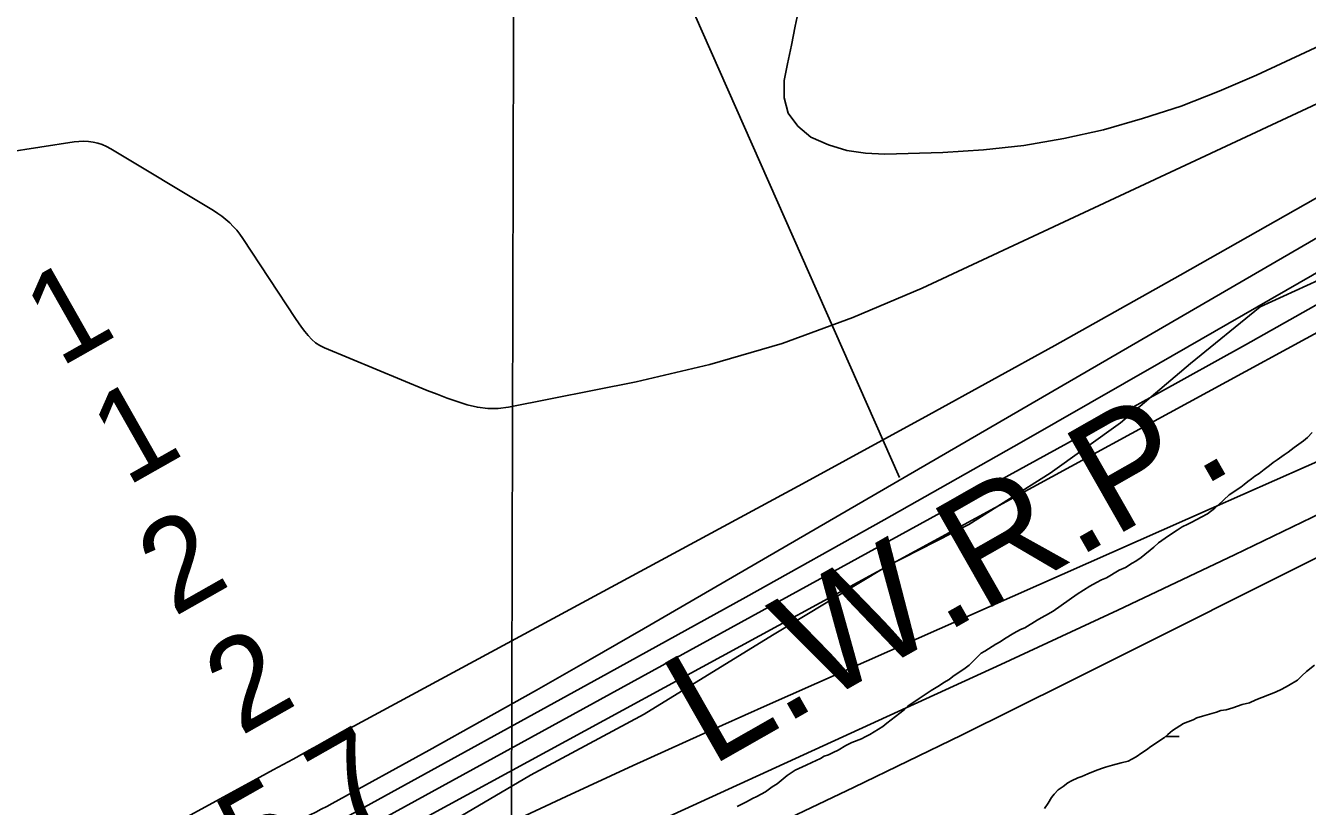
# Model space of a CAD drawing. Extents: x 3177385 to 3215275, y 903885 to 929304.
# Drawn here: x 3191696 to 3192634, y 910384 to 910956 of the extents above; entities that cross this region are included whole.
import ezdxf

# ---------------------------------------------------------------- set-up
doc = ezdxf.new("R2010")
doc.units = 0
for name, color, linetype in [('V-GRID-MAJR', 7, 'Continuous'), ('V-RIVR-EDGE', 7, 'Continuous'), ('V-RIVR-RANG', 7, 'Continuous'), ('V-SITE-VEGE', 7, 'Continuous'), ('V-TOPO-DPTH', 7, 'Continuous'), ('V-TOPO-MAJR', 7, 'Continuous'), ('V-TOPO-MINR', 7, 'Continuous'), ('V-TOPO-WATR', 7, 'Continuous'), ('V-TOPO-WATR-IDEN', 7, 'Continuous'), ('V-WETL-SWMP', 7, 'Continuous')]:
    doc.layers.add(name, color=color, linetype=linetype)

msp = doc.modelspace()

# ---------------------------------------------------------------- linework, layer by layer
at = {"layer": 'V-GRID-MAJR'}
msp.add_spline([(3192048.7, 909312.78), (3192063.69, 915372.62), (3192078.68, 921435.55), (3192093.67, 927498.52), (3192093.68, 927501.56)], degree=3, dxfattribs=at)
at = {"layer": 'V-RIVR-EDGE'}
msp.add_lwpolyline([(3191682.14, 910203.16), (3191755.71, 910245.57), (3191792.71, 910266.35), (3191827.54, 910288.86), (3191886.7, 910308.28), (3191936.3, 910326.85), (3191958.94, 910340.7), (3191997.69, 910367.55), (3192065.17, 910407.38), (3192148.3, 910451.94), (3192242.33, 910509.96), (3192325.92, 910560.17), (3192385.98, 910590.89), (3192445.62, 910628.56), (3192497.01, 910665.38), (3192548.4, 910708.72), (3192599.37, 910750.32), (3192650.72, 910773.67)], dxfattribs=at)
at = {"layer": 'V-RIVR-RANG'}
msp.add_line((3192335.41, 910625.19), (3191971.39, 911448.29), dxfattribs=at)
at = {"layer": 'V-SITE-VEGE'}
for p, q in [((3192637.48, 910658.32), (3192633.91, 910654.68)), ((3192624.36, 910647.24), (3192619.92, 910643.84)), ((3192631.01, 910652.12), (3192624.36, 910647.24)), ((3192633.91, 910654.68), (3192631.01, 910652.12)), ((3192608.84, 910636.22), (3192606.17, 910634.09)), ((3192611.72, 910638.12), (3192608.84, 910636.22)), ((3192617.04, 910641.94), (3192611.72, 910638.12)), ((3192619.92, 910643.84), (3192617.04, 910641.94)), ((3192598.62, 910628.14), (3192595.52, 910626.24)), ((3192602.18, 910631.12), (3192598.62, 910628.14)), ((3192606.17, 910634.09), (3192602.18, 910631.12)), ((3192585.31, 910618.16), (3192576.68, 910612.66)), ((3192587.76, 910620.29), (3192585.31, 910618.16)), ((3192590.42, 910622.42), (3192587.76, 910620.29)), ((3192593.08, 910624.32), (3192590.42, 910622.42)), ((3192595.52, 910626.24), (3192593.08, 910624.32)), ((3192576.68, 910612.66), (3192568.65, 910604.97)), ((3192560.87, 910598.59), (3192556.24, 910596.29)), ((3192566.2, 910602.84), (3192560.87, 910598.59)), ((3192568.65, 910604.97), (3192566.2, 910602.84)), ((3192542.33, 910589.16), (3192538.57, 910586.83)), ((3192546.52, 910591.03), (3192542.33, 910589.16)), ((3192549.39, 910592.5), (3192546.52, 910591.03)), ((3192556.24, 910596.29), (3192549.39, 910592.5)), ((3192532.14, 910582.6), (3192525.05, 910577.52)), ((3192538.57, 910586.83), (3192532.14, 910582.6)), ((3192521.48, 910574.31), (3192512.15, 910566.65)), ((3192525.05, 910577.52), (3192521.48, 910574.31)), ((3192505.73, 910562.64), (3192500.86, 910559.47)), ((3192508.38, 910564.11), (3192505.73, 910562.64)), ((3192512.15, 910566.65), (3192508.38, 910564.11)), ((3192486.94, 910551.9), (3192483.2, 910550.46)), ((3192496.23, 910557.38), (3192486.94, 910551.9)), ((3192500.86, 910559.47), (3192496.23, 910557.38)), ((3192474.58, 910545.83), (3192465.29, 910539.92)), ((3192479.44, 910548.35), (3192474.58, 910545.83)), ((3192483.2, 910550.46), (3192479.44, 910548.35)), ((3192465.29, 910539.92), (3192447.77, 910527.41)), ((3192442.24, 910524.25), (3192438.93, 910522.57)), ((3192447.77, 910527.41), (3192442.24, 910524.25)), ((3192426.98, 910515.18), (3192423.9, 910513.94)), ((3192436.06, 910520.89), (3192426.98, 910515.18)), ((3192438.93, 910522.57), (3192436.06, 910520.89)), ((3192409.08, 910504.86), (3192405.76, 910503.19)), ((3192412.18, 910507.2), (3192409.08, 910504.86)), ((3192419.04, 910511.42), (3192412.18, 910507.2)), ((3192423.9, 910513.94), (3192419.04, 910511.42)), ((3192395.14, 910496.65), (3192390.68, 910492.37)), ((3192397.79, 910498.12), (3192395.14, 910496.65)), ((3192405.76, 910503.19), (3192397.79, 910498.12)), ((3192386.22, 910487.88), (3192383.33, 910485.76)), ((3192388.45, 910490.02), (3192386.22, 910487.88)), ((3192390.68, 910492.37), (3192388.45, 910490.02)), ((3192371.58, 910477.28), (3192367.83, 910475.17)), ((3192374.47, 910479.62), (3192371.58, 910477.28)), ((3192383.33, 910485.76), (3192374.47, 910479.62)), ((3192358.53, 910469.26), (3192352.77, 910465.45)), ((3192364.72, 910473.06), (3192358.53, 910469.26)), ((3192367.83, 910475.17), (3192364.72, 910473.06)), ((3192341.47, 910457.83), (3192338.79, 910455.26)), ((3192349.67, 910463.55), (3192341.47, 910457.83)), ((3192352.77, 910465.45), (3192349.67, 910463.55)), ((3192335.68, 910452.71), (3192326.14, 910445.49)), ((3192338.79, 910455.26), (3192335.68, 910452.71)), ((3192323.03, 910442.94), (3192313.51, 910437.02)), ((3192326.14, 910445.49), (3192323.03, 910442.94)), ((3192300.5, 910431.19), (3192296.09, 910429.09)), ((3192307.55, 910433.87), (3192300.5, 910431.19)), ((3192310.2, 910435.35), (3192307.55, 910433.87)), ((3192313.51, 910437.02), (3192310.2, 910435.35)), ((3192280.2, 910421.14), (3192277.55, 910419.66)), ((3192283.28, 910422.16), (3192280.2, 910421.14)), ((3192286.81, 910423.84), (3192283.28, 910422.16)), ((3192290.34, 910425.72), (3192286.81, 910423.84)), ((3192296.09, 910429.09), (3192290.34, 910425.72)), ((3192259.02, 910410.89), (3192253.04, 910407.08)), ((3192266.96, 910414.65), (3192259.02, 910410.89)), ((3192271.15, 910416.74), (3192266.96, 910414.65)), ((3192277.55, 910419.66), (3192271.15, 910416.74)), ((3192253.04, 910407.08), (3192245.7, 910400.91)), ((3192237.28, 910395.19), (3192230.87, 910391.62)), ((3192242.17, 910398.8), (3192237.28, 910395.19)), ((3192245.7, 910400.91), (3192242.17, 910398.8)), ((3192223.37, 910387.84), (3192216.53, 910384.5)), ((3192227.79, 910390.15), (3192223.37, 910387.84)), ((3192230.87, 910391.62), (3192227.79, 910390.15))]:
    msp.add_line(p, q, dxfattribs=at)
at = {"layer": 'V-TOPO-DPTH'}
for points in [[(3192750.22, 910991.65), (3192596.7, 910919.95), (3192569.34, 910908.1), (3192541.61, 910897.31), (3192513.31, 910888.11), (3192484.63, 910879.96), (3192455.54, 910873.57), (3192426.26, 910868.47), (3192396.71, 910865.29), (3192366.98, 910863.39), (3192324.53, 910862.06), (3192310.47, 910862.73), (3192296.72, 910864.79), (3192283.47, 910868.96), (3192270.53, 910874.54), (3192260.8, 910882.61), (3192253.83, 910891.99), (3192251.01, 910903.33), (3192250.96, 910915.98), (3192253.46, 910928.15), (3192256.28, 910941.95), (3192259.06, 910955.76), (3192261.79, 910969.57)], [(3192750.22, 910991.65), (3192596.7, 910919.95), (3192569.34, 910908.1), (3192541.61, 910897.31), (3192513.31, 910888.11), (3192484.63, 910879.96), (3192455.54, 910873.57), (3192426.26, 910868.47), (3192396.71, 910865.29), (3192366.98, 910863.39), (3192324.53, 910862.06), (3192310.47, 910862.73), (3192296.72, 910864.79), (3192283.47, 910868.96), (3192270.53, 910874.54), (3192260.8, 910882.61), (3192253.83, 910891.99), (3192251.01, 910903.33), (3192250.96, 910915.98), (3192253.46, 910928.15), (3192256.28, 910941.95), (3192259.06, 910955.76), (3192261.79, 910969.57)], [(3190594.76, 909767.6), (3190671.75, 909798.31), (3190886.03, 909887.07), (3190887.1, 909887.53), (3190890.24, 909888.99), (3191053.07, 909970.07), (3191135.29, 910011.58), (3191217.19, 910053.7), (3191298.62, 910096.72), (3191379.74, 910140.34), (3191862.17, 910403.27), (3191876.76, 910411.21), (3191891.35, 910419.14), (3191905.95, 910427.05), (3191920.56, 910434.96), (3192264.2, 910620.72), (3192356.7, 910671.14), (3192448.97, 910721.98), (3192540.88, 910773.46), (3192632.56, 910825.36), (3192780.37, 910909.72)], [(3192780.37, 910909.72), (3192632.56, 910825.36), (3192540.88, 910773.46), (3192448.97, 910721.98), (3192356.7, 910671.14), (3192264.2, 910620.72), (3191920.56, 910434.96), (3191905.95, 910427.05), (3191891.35, 910419.14), (3191876.76, 910411.21), (3191862.17, 910403.27), (3191379.74, 910140.34), (3191298.62, 910096.72), (3191217.19, 910053.7), (3191135.29, 910011.58), (3191053.07, 909970.07), (3190890.24, 909888.99), (3190887.1, 909887.53), (3190886.03, 909887.07), (3190671.75, 909798.31), (3190594.76, 909767.6)], [(3190773.81, 909825.22), (3190881.11, 909873.05), (3190887.07, 909875.73), (3190893.01, 909878.44), (3190898.94, 909881.19), (3190904.85, 909883.96), (3191537.07, 910183.08), (3191601.03, 910213.58), (3191664.85, 910244.35), (3191728.49, 910275.51), (3191791.99, 910306.94), (3191898.29, 910359.95), (3191908.52, 910365.13), (3191918.71, 910370.39), (3191928.83, 910375.77), (3191938.91, 910381.24), (3192121.67, 910481.72), (3192222.94, 910537.78), (3192323.99, 910594.23), (3192424.7, 910651.27), (3192525.2, 910708.7), (3192802.32, 910868.12)], [(3192802.32, 910868.12), (3192525.2, 910708.7), (3192424.7, 910651.27), (3192323.99, 910594.23), (3192222.94, 910537.78), (3192121.67, 910481.72), (3191938.91, 910381.24), (3191928.83, 910375.77), (3191918.71, 910370.39), (3191908.52, 910365.13), (3191898.29, 910359.95), (3191791.99, 910306.94), (3191728.49, 910275.51), (3191664.85, 910244.35), (3191601.03, 910213.58), (3191537.07, 910183.08), (3190904.85, 909883.96), (3190898.94, 909881.19), (3190893.01, 909878.44), (3190887.07, 909875.73), (3190881.11, 909873.05), (3190773.81, 909825.22)], [(3189907.85, 909317.76), (3190786.54, 909802.18), (3190846.26, 909830.37), (3190874.99, 909843.88), (3190903.74, 909857.33), (3190932.53, 909870.71), (3190961.34, 909884.03), (3191160.92, 909975.94), (3191289.34, 910035.62), (3191417.47, 910095.9), (3191545.17, 910157.07), (3191672.6, 910218.83), (3191886.81, 910323.58), (3191909.55, 910334.88), (3191932.19, 910346.38), (3191954.68, 910358.18), (3191977.06, 910370.17), (3192774.87, 910804.33)]]:
    msp.add_lwpolyline(points, dxfattribs=at)
at = {"layer": 'V-TOPO-MAJR'}
msp.add_lwpolyline([(3191330.66, 909999.44), (3191930.38, 910227.54), (3191958.09, 910239.21), (3191985.69, 910251.11), (3192013.15, 910263.35), (3192040.51, 910275.81), (3192144.35, 910323.91), (3192223.38, 910360.95), (3192302.17, 910398.48), (3192380.62, 910436.73), (3192458.83, 910475.47), (3192878.95, 910685.93)], dxfattribs=at)
at = {"layer": 'V-TOPO-MINR'}
for points in [[(3192261.79, 910969.57), (3192259.06, 910955.76), (3192256.28, 910941.95), (3192253.46, 910928.15), (3192250.96, 910915.98), (3192251.01, 910903.33), (3192253.83, 910891.99), (3192260.8, 910882.61), (3192270.53, 910874.54), (3192283.47, 910868.96), (3192296.72, 910864.79), (3192310.47, 910862.73), (3192324.53, 910862.06), (3192366.98, 910863.39), (3192396.71, 910865.29), (3192426.26, 910868.47), (3192455.54, 910873.57), (3192484.63, 910879.96), (3192513.31, 910888.11), (3192541.61, 910897.31), (3192569.34, 910908.1), (3192596.7, 910919.95), (3192750.22, 910991.65)], [(3191680.9, 910863.18), (3191731.16, 910870.99), (3191734.63, 910871.36), (3191738.09, 910871.49), (3191741.56, 910871.29), (3191745.01, 910870.86), (3191748.4, 910870.07), (3191751.7, 910869.04), (3191754.87, 910867.65), (3191757.94, 910866.03), (3191833.13, 910820.75), (3191836.27, 910818.72), (3191839.31, 910816.57), (3191842.2, 910814.22), (3191845, 910811.74), (3191847.62, 910809.08), (3191850.11, 910806.31), (3191852.41, 910803.38), (3191854.57, 910800.33), (3191893.23, 910741.65), (3191895.41, 910738.45), (3191897.66, 910735.31), (3191900, 910732.24), (3191902.42, 910729.22), (3191905.06, 910726.47), (3191907.92, 910724.02), (3191911.1, 910722), (3191914.5, 910720.29), (3191989.63, 910689.12), (3191996.87, 910686.23), (3192004.15, 910683.47), (3192011.51, 910680.91), (3192018.92, 910678.47), (3192026.39, 910676.74), (3192033.91, 910675.76), (3192041.48, 910675.92), (3192049.1, 910676.84), (3192142.61, 910695.42), (3192196.39, 910708.14), (3192249.34, 910723.39), (3192301.05, 910742.42), (3192351.93, 910763.98), (3192733.77, 910942.32)], [(3190594.76, 909767.6), (3190671.75, 909798.31), (3190886.03, 909887.07), (3190887.1, 909887.53), (3190890.24, 909888.99), (3191053.07, 909970.07), (3191135.29, 910011.58), (3191217.19, 910053.7), (3191298.62, 910096.72), (3191379.74, 910140.34), (3191862.17, 910403.27), (3191876.76, 910411.21), (3191891.35, 910419.14), (3191905.95, 910427.05), (3191920.56, 910434.96), (3192264.2, 910620.72), (3192356.7, 910671.14), (3192448.97, 910721.98), (3192540.88, 910773.46), (3192632.56, 910825.36), (3192780.37, 910909.72)], [(3189797.72, 909318.02), (3190760.57, 909827.55), (3190883.54, 909880.14), (3190887.06, 909881.68), (3190890.57, 909883.25), (3190894.05, 909884.88), (3190897.52, 909886.53), (3191753.14, 910303.1), (3191779.72, 910316.11), (3191806.26, 910329.19), (3191832.74, 910342.37), (3191859.19, 910355.64), (3191903.92, 910378.18), (3191907.97, 910380.25), (3191912, 910382.34), (3191916, 910384.48), (3191919.99, 910386.65), (3191990.96, 910425.75), (3192030.35, 910447.62), (3192069.63, 910469.67), (3192108.77, 910491.99), (3192147.81, 910514.47), (3192771.73, 910876.71)], [(3189907.85, 909317.76), (3190786.54, 909802.18), (3190846.26, 909830.37), (3190874.99, 909843.88), (3190903.74, 909857.33), (3190932.53, 909870.71), (3190961.34, 909884.03), (3191160.92, 909975.94), (3191289.34, 910035.62), (3191417.47, 910095.9), (3191545.17, 910157.07), (3191672.6, 910218.83), (3191886.81, 910323.58), (3191909.55, 910334.88), (3191932.19, 910346.38), (3191954.68, 910358.18), (3191977.06, 910370.17), (3192774.87, 910804.33)], [(3189871.82, 909317.84), (3190780.45, 909815.09), (3190876.44, 909859.27), (3190887.1, 909864.19), (3190897.76, 909869.11), (3190908.41, 909874.04), (3190919.06, 909878.99), (3191339.99, 910074.62), (3191438.17, 910120.67), (3191536.12, 910167.19), (3191633.74, 910214.4), (3191731.13, 910262.07), (3191892.61, 910341.82), (3191909.04, 910350.07), (3191925.41, 910358.46), (3191941.66, 910367.06), (3191957.84, 910375.8), (3192458.26, 910650.34), (3192523.47, 910686.32), (3192588.58, 910722.5), (3192653.51, 910758.98)], [(3190790.59, 909788.07), (3190864.2, 909823.81), (3190886.93, 909834.75), (3190909.71, 909845.58), (3190932.57, 909856.25), (3190955.48, 909866.81), (3191108.63, 909936.75), (3191208.12, 909982.27), (3191307.56, 910027.91), (3191406.92, 910073.72), (3191506.23, 910119.63), (3191875.4, 910290.66), (3191910.32, 910306.88), (3191945.21, 910323.16), (3191980.07, 910339.51), (3192014.91, 910355.91), (3192042.63, 910369), (3192091.39, 910391.8), (3192140.26, 910414.38), (3192189.29, 910436.59), (3192238.43, 910458.58), (3192563.59, 910602.63), (3192609.86, 910623.15), (3192656.13, 910643.68)], [(3191693.89, 910175.76), (3191723.31, 910187.89), (3191752.87, 910199.65), (3191782.54, 910211.16), (3191812.23, 910222.62), (3191841.86, 910234.25), (3191871.38, 910246.13), (3191900.83, 910258.19), (3191947.75, 910277.64), (3191957.05, 910281.56), (3191966.33, 910285.54), (3191975.55, 910289.63), (3191984.75, 910293.79), (3192409.43, 910488.5), (3192495.07, 910528.26), (3192580.45, 910568.56), (3192665.44, 910609.67)]]:
    msp.add_lwpolyline(points, dxfattribs=at)
at = {"layer": 'V-TOPO-WATR'}
msp.add_lwpolyline([(3190773.81, 909825.22), (3190881.11, 909873.05), (3190887.07, 909875.73), (3190893.01, 909878.44), (3190898.94, 909881.19), (3190904.85, 909883.96), (3191537.07, 910183.08), (3191601.03, 910213.58), (3191664.85, 910244.35), (3191728.49, 910275.51), (3191791.99, 910306.94), (3191898.29, 910359.95), (3191908.52, 910365.13), (3191918.71, 910370.39), (3191928.83, 910375.77), (3191938.91, 910381.24), (3192121.67, 910481.72), (3192222.94, 910537.78), (3192323.99, 910594.23), (3192424.7, 910651.27), (3192525.2, 910708.7), (3192802.32, 910868.12)], dxfattribs=at)
at = {"layer": 'V-WETL-SWMP'}
msp.add_line((3192530.22, 910435.69), (3192540, 910435.67), dxfattribs=at)
msp.add_lwpolyline([(3192441.36, 910383.01), (3192444.11, 910386.76), (3192446.49, 910390.9), (3192448.45, 910393.53), (3192451.56, 910396.51), (3192455.05, 910399.1), (3192458.53, 910401.7), (3192461.23, 910403.17), (3192465.85, 910405.35), (3192468.92, 910406.43), (3192473.15, 910408.25), (3192478.54, 910410.42), (3192483.15, 910412.23), (3192486.22, 910413.3), (3192491.2, 910414.72), (3192497.72, 910416.49), (3192502.7, 910417.53), (3192505.4, 910418.99), (3192508.48, 910420.83), (3192512.74, 910423.79), (3192516.22, 910426.01), (3192519.31, 910428.23), (3192522.02, 910430.07), (3192525.89, 910432.66), (3192529.36, 910434.87), (3192531.7, 910437.11), (3192535.19, 910440.08), (3192543.31, 910445.25), (3192546.38, 910446.33), (3192550.22, 910447.77), (3192552.92, 910449.23), (3192557.14, 910450.67), (3192564.04, 910452.43), (3192567.49, 910453.5), (3192570.57, 910454.58), (3192574.39, 910455.26), (3192579.38, 910456.68), (3192586.29, 910459.2), (3192591.65, 910460.23), (3192596.27, 910462.41), (3192610.49, 910468.21), (3192615.11, 910470.4), (3192620.12, 910472.96), (3192626.69, 910477.01), (3192629.8, 910479.99), (3192633.3, 910483.35), (3192639.11, 910487.8)], dxfattribs=at)

# ---------------------------------------------------------------- texts
at = {"layer": 'V-RIVR-RANG'}
for s, p in [('1', (3191720.59, 910705.48)), ('1', (3191769.51, 910618.26)), ('2', (3191803.98, 910522.86)), ('2', (3191852.91, 910435.65)), ('5.7', (3191862.36, 910326.07))]:
    msp.add_text(s, height=67, rotation=29.53194, dxfattribs=at).set_placement(p)
at = {"layer": 'V-TOPO-WATR-IDEN'}
msp.add_text('L.W.R.P.', height=83, rotation=29.66501, dxfattribs=at).set_placement((3192196.84, 910413.14))

doc.saveas('drawing.dxf')
